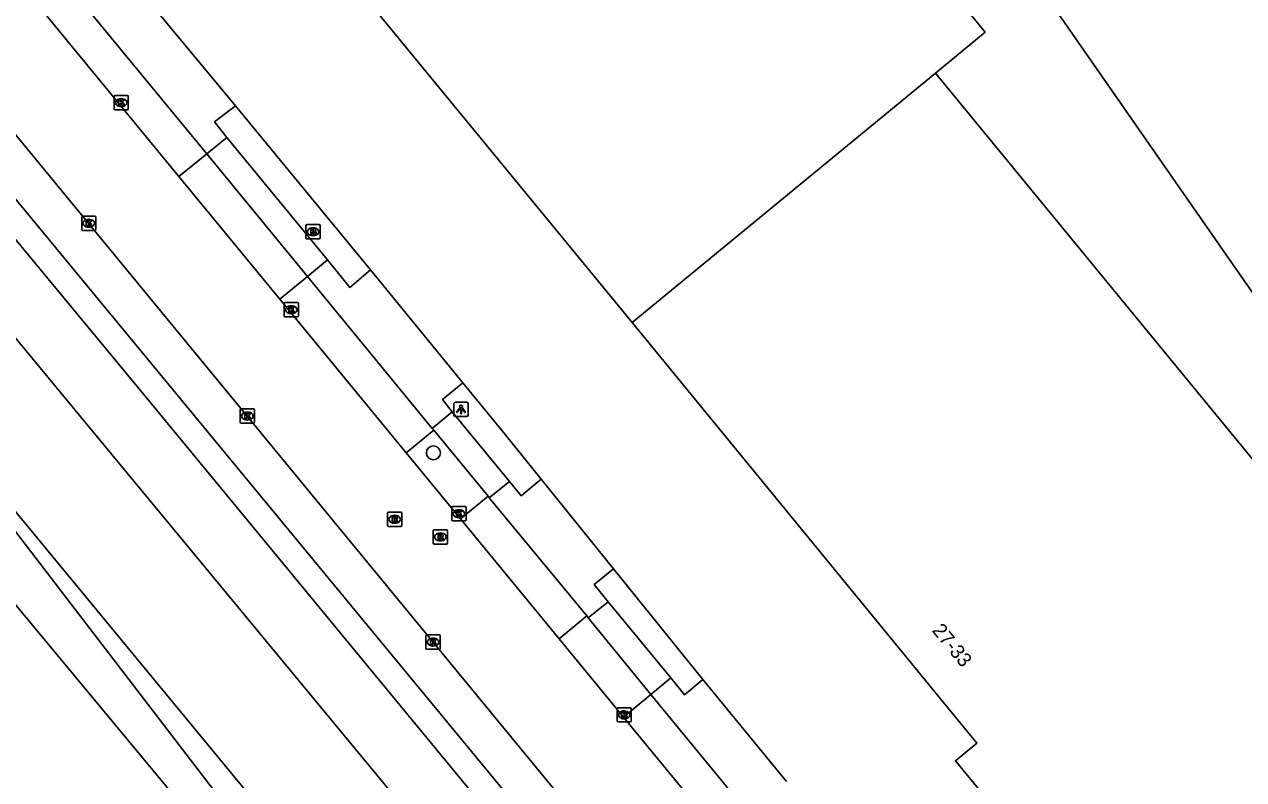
# Model space of a CAD drawing. Extents: x 156651 to 158072, y 387631 to 388990.
# Drawn here: x 157276.7 to 157362.3, y 387691.7 to 387744.8 of the extents above; entities that cross this region are included whole.
import ezdxf

# ---------------------------------------------------------------- set-up
doc = ezdxf.new("R2010")
doc.units = 0
for name, color, linetype in [('IMGEO_Berm_groen', 7, 'Continuous'), ('IMGEO_Boom', 7, 'Continuous'), ('IMGEO_Brandkraan', 7, 'Continuous'), ('IMGEO_Groenvoorziening', 7, 'Continuous'), ('IMGEO_Hek', 7, 'Continuous'), ('IMGEO_Kolk', 7, 'Continuous'), ('IMGEO_Lichtpunt', 7, 'Continuous'), ('IMGEO_Pand', 7, 'Continuous'), ('IMGEO_Pand_nummerreeks', 7, 'Continuous'), ('IMGEO_Rijbaan_lokaal_gesloten', 7, 'Continuous'), ('IMGEO_Rioolput', 7, 'Continuous'), ('IMGEO_Spoor', 7, 'Continuous'), ('IMGEO_Spoorbaan_halfverhard', 7, 'Continuous'), ('IMGEO_Voetpad_open', 7, 'Continuous')]:
    doc.layers.add(name, color=color, linetype=linetype)

msp = doc.modelspace()

# ---------------------------------------------------------------- linework, layer by layer
at = {"layer": 'IMGEO_Berm_groen'}
msp.add_lwpolyline([(157166.96, 387864.35), (157177.251, 387852.02), (157242.391, 387773.236), (157261.602, 387750), (157335.27, 387660.718)], dxfattribs=at)
at = {"layer": 'IMGEO_Boom'}
msp.add_circle((157305.393, 387714.675), 0.489, dxfattribs=at)
at = {"layer": 'IMGEO_Brandkraan'}
for p, q in [((157296.439, 387729.781), (157296.439, 387730.633)), ((157296.514, 387730.707), (157297.366, 387730.707)), ((157296.927, 387730.487), (157296.952, 387730.487)), ((157297.44, 387730.633), (157297.44, 387729.781)), ((157297.366, 387729.707), (157296.514, 387729.707)), ((157296.95, 387729.927), (157296.925, 387729.927))]:
    msp.add_line(p, q, dxfattribs=at)
for points in [[(157296.439, 387729.781), (157296.439, 387730.633)], [(157296.514, 387730.707), (157297.366, 387730.707)], [(157297.44, 387730.633), (157297.44, 387729.781)], [(157297.366, 387729.707), (157296.514, 387729.707)], [(157296.787, 387730.407), (157296.787, 387730.007), (157297, 387730.007)], [(157297.018, 387730.407), (157296.787, 387730.407)], [(157296.966, 387730.326), (157296.912, 387730.326), (157296.912, 387730.25)], [(157296.912, 387730.25), (157296.965, 387730.25)], [(157296.974, 387730.174), (157296.912, 387730.174), (157296.912, 387730.093)], [(157296.912, 387730.093), (157296.974, 387730.093)]]:
    msp.add_lwpolyline(points, dxfattribs=at)
for centre, radius, start, end in [((157296.516, 387730.631), 0.0765, 91.55205, 178.44795), ((157296.516, 387730.631), 0.0765, 91.55205, 178.44795), ((157297.364, 387730.631), 0.0765, 1.55205, 88.44795), ((157297.364, 387730.631), 0.0765, 1.55205, 88.44795), ((157296.516, 387729.783), 0.0765, 181.55205, 268.44795), ((157296.516, 387729.783), 0.0765, 181.55205, 268.44795), ((157296.967, 387730.288), 0.0379, 267.82845, 90.93552), ((157296.975, 387730.133), 0.0404, 269.87594, 90.50774), ((157297.006, 387730.258), 0.251, 268.66757, 293.53466), ((157297.022, 387730.262), 0.145, 59.4692, 91.53667), ((157297.047, 387730.309), 0.0922, 285.51372, 58.15012), ((157297.052, 387730.117), 0.105, 301.31148, 78.98903), ((157297.364, 387729.783), 0.0765, 271.55205, 358.44795), ((157297.364, 387729.783), 0.0765, 271.55205, 358.44795)]:
    msp.add_arc(centre, radius, start, end, dxfattribs=at)
for centre, major_axis, ratio, start_param, end_param in [((157296.926, 387730.207), (-0.387, 0.002), 0.722429, 4.712389, 7.853982), ((157296.951, 387730.207), (-0.39, 0.002), 0.717154, 1.570796, 4.712389)]:
    msp.add_ellipse(centre, major_axis=major_axis, ratio=ratio, start_param=start_param, end_param=end_param, dxfattribs=at)
at = {"layer": 'IMGEO_Groenvoorziening'}
for points in [[(157300.967, 387727.542), (157291.488, 387739.063)], [(157312.956, 387712.823), (157310.43, 387715.954), (157307.465, 387719.585)], [(157324.314, 387698.743), (157318.033, 387706.529)]]:
    msp.add_lwpolyline(points, dxfattribs=at)
at = {"layer": 'IMGEO_Hek'}
for points in [[(157312.956, 387712.823), (157310.43, 387715.954)], [(157318.033, 387706.529), (157312.956, 387712.823)], [(157324.314, 387698.743), (157318.033, 387706.529)], [(157330.19, 387691.592), (157324.314, 387698.743)]]:
    msp.add_lwpolyline(points, dxfattribs=at)
at = {"layer": 'IMGEO_Kolk'}
for p, q in [((157282.963, 387738.851), (157282.963, 387739.703)), ((157283.038, 387739.777), (157283.89, 387739.777)), ((157283.451, 387739.557), (157283.476, 387739.557)), ((157283.964, 387739.703), (157283.964, 387738.851)), ((157283.89, 387738.777), (157283.038, 387738.777)), ((157283.474, 387738.997), (157283.449, 387738.997)), ((157280.69, 387730.376), (157280.69, 387731.228)), ((157280.765, 387731.302), (157281.617, 387731.302)), ((157281.201, 387730.522), (157281.176, 387730.522)), ((157281.178, 387731.082), (157281.203, 387731.082)), ((157281.691, 387731.228), (157281.691, 387730.376)), ((157281.617, 387730.302), (157280.765, 387730.302)), ((157294.912, 387724.304), (157294.912, 387725.156)), ((157294.987, 387725.23), (157295.839, 387725.23)), ((157295.4, 387725.01), (157295.425, 387725.01)), ((157295.913, 387725.156), (157295.913, 387724.304)), ((157295.839, 387724.23), (157294.987, 387724.23)), ((157295.423, 387724.45), (157295.398, 387724.45)), ((157291.827, 387716.832), (157291.827, 387717.684)), ((157291.902, 387717.758), (157292.754, 387717.758)), ((157292.828, 387717.684), (157292.828, 387716.832)), ((157292.754, 387716.758), (157291.902, 387716.758)), ((157292.338, 387716.978), (157292.313, 387716.978)), ((157292.315, 387717.538), (157292.34, 387717.538)), ((157306.687, 387709.972), (157306.687, 387710.824)), ((157306.762, 387710.898), (157307.614, 387710.898)), ((157307.688, 387710.824), (157307.688, 387709.972)), ((157307.198, 387710.118), (157307.173, 387710.118)), ((157307.175, 387710.678), (157307.2, 387710.678)), ((157307.614, 387709.898), (157306.762, 387709.898)), ((157304.867, 387700.958), (157304.867, 387701.81)), ((157304.942, 387701.884), (157305.794, 387701.884)), ((157305.355, 387701.664), (157305.38, 387701.664)), ((157305.868, 387701.81), (157305.868, 387700.958)), ((157305.794, 387700.884), (157304.942, 387700.884)), ((157305.378, 387701.104), (157305.353, 387701.104)), ((157318.293, 387695.844), (157318.293, 387696.696)), ((157318.368, 387696.77), (157319.22, 387696.77)), ((157318.781, 387696.55), (157318.806, 387696.55)), ((157319.294, 387696.696), (157319.294, 387695.844)), ((157319.22, 387695.77), (157318.368, 387695.77)), ((157318.804, 387695.99), (157318.779, 387695.99))]:
    msp.add_line(p, q, dxfattribs=at)
for points in [[(157282.963, 387738.851), (157282.963, 387739.703)], [(157283.038, 387739.777), (157283.89, 387739.777)], [(157283.284, 387739.477), (157283.407, 387739.477), (157283.407, 387739.326), (157283.537, 387739.477), (157283.701, 387739.477), (157283.555, 387739.326), (157283.708, 387739.077), (157283.556, 387739.077), (157283.471, 387739.241), (157283.407, 387739.174), (157283.407, 387739.077), (157283.284, 387739.077), (157283.284, 387739.477)], [(157283.964, 387739.703), (157283.964, 387738.851)], [(157283.89, 387738.777), (157283.038, 387738.777)], [(157280.69, 387730.376), (157280.69, 387731.228)], [(157280.765, 387731.302), (157281.617, 387731.302)], [(157281.011, 387731.002), (157281.134, 387731.002), (157281.134, 387730.851), (157281.264, 387731.002), (157281.428, 387731.002), (157281.282, 387730.851), (157281.435, 387730.602), (157281.283, 387730.602), (157281.198, 387730.766), (157281.134, 387730.699), (157281.134, 387730.602), (157281.011, 387730.602), (157281.011, 387731.002)], [(157281.691, 387731.228), (157281.691, 387730.376)], [(157281.617, 387730.302), (157280.765, 387730.302)], [(157294.912, 387724.304), (157294.912, 387725.156)], [(157294.987, 387725.23), (157295.839, 387725.23)], [(157295.233, 387724.93), (157295.356, 387724.93), (157295.356, 387724.779), (157295.486, 387724.93), (157295.65, 387724.93), (157295.504, 387724.779), (157295.657, 387724.53), (157295.505, 387724.53), (157295.42, 387724.694), (157295.356, 387724.627), (157295.356, 387724.53), (157295.233, 387724.53), (157295.233, 387724.93)], [(157295.913, 387725.156), (157295.913, 387724.304)], [(157295.839, 387724.23), (157294.987, 387724.23)], [(157291.827, 387716.832), (157291.827, 387717.684)], [(157291.902, 387717.758), (157292.754, 387717.758)], [(157292.828, 387717.684), (157292.828, 387716.832)], [(157292.754, 387716.758), (157291.902, 387716.758)], [(157292.148, 387717.458), (157292.271, 387717.458), (157292.271, 387717.307), (157292.401, 387717.458), (157292.565, 387717.458), (157292.419, 387717.307), (157292.572, 387717.058), (157292.42, 387717.058), (157292.335, 387717.222), (157292.271, 387717.155), (157292.271, 387717.058), (157292.148, 387717.058), (157292.148, 387717.458)], [(157306.687, 387709.972), (157306.687, 387710.824)], [(157306.762, 387710.898), (157307.614, 387710.898)], [(157307.688, 387710.824), (157307.688, 387709.972)], [(157307.008, 387710.598), (157307.131, 387710.598), (157307.131, 387710.447), (157307.261, 387710.598), (157307.425, 387710.598), (157307.279, 387710.447), (157307.432, 387710.198), (157307.28, 387710.198), (157307.195, 387710.362), (157307.131, 387710.295), (157307.131, 387710.198), (157307.008, 387710.198), (157307.008, 387710.598)], [(157307.614, 387709.898), (157306.762, 387709.898)], [(157304.867, 387700.958), (157304.867, 387701.81)], [(157304.942, 387701.884), (157305.794, 387701.884)], [(157305.188, 387701.584), (157305.311, 387701.584), (157305.311, 387701.433), (157305.441, 387701.584), (157305.605, 387701.584), (157305.459, 387701.433), (157305.612, 387701.184), (157305.46, 387701.184), (157305.375, 387701.348), (157305.311, 387701.281), (157305.311, 387701.184), (157305.188, 387701.184), (157305.188, 387701.584)], [(157305.868, 387701.81), (157305.868, 387700.958)], [(157305.794, 387700.884), (157304.942, 387700.884)], [(157318.293, 387695.844), (157318.293, 387696.696)], [(157318.368, 387696.77), (157319.22, 387696.77)], [(157318.614, 387696.47), (157318.737, 387696.47), (157318.737, 387696.319), (157318.867, 387696.47), (157319.031, 387696.47), (157318.885, 387696.319), (157319.038, 387696.07), (157318.886, 387696.07), (157318.801, 387696.234), (157318.737, 387696.167), (157318.737, 387696.07), (157318.614, 387696.07), (157318.614, 387696.47)], [(157319.294, 387696.696), (157319.294, 387695.844)], [(157319.22, 387695.77), (157318.368, 387695.77)]]:
    msp.add_lwpolyline(points, dxfattribs=at)
for centre, start, end in [((157283.04, 387739.701), 91.55205, 178.44795), ((157283.04, 387739.701), 91.55205, 178.44795), ((157283.888, 387739.701), 1.55205, 88.44795), ((157283.888, 387739.701), 1.55205, 88.44795), ((157283.04, 387738.853), 181.55205, 268.44795), ((157283.04, 387738.853), 181.55205, 268.44795), ((157283.888, 387738.853), 271.55205, 358.44795), ((157283.888, 387738.853), 271.55205, 358.44795), ((157280.767, 387731.226), 91.55205, 178.44795), ((157280.767, 387731.226), 91.55205, 178.44795), ((157281.615, 387731.226), 1.55205, 88.44795), ((157281.615, 387731.226), 1.55205, 88.44795), ((157280.767, 387730.378), 181.55205, 268.44795), ((157280.767, 387730.378), 181.55205, 268.44795), ((157281.615, 387730.378), 271.55205, 358.44795), ((157281.615, 387730.378), 271.55205, 358.44795), ((157294.989, 387725.154), 91.55205, 178.44795), ((157294.989, 387725.154), 91.55205, 178.44795), ((157295.837, 387725.154), 1.55205, 88.44795), ((157295.837, 387725.154), 1.55205, 88.44795), ((157294.989, 387724.306), 181.55205, 268.44795), ((157294.989, 387724.306), 181.55205, 268.44795), ((157295.837, 387724.306), 271.55205, 358.44795), ((157295.837, 387724.306), 271.55205, 358.44795), ((157291.904, 387717.682), 91.55205, 178.44795), ((157291.904, 387717.682), 91.55205, 178.44795), ((157292.752, 387717.682), 1.55205, 88.44795), ((157292.752, 387717.682), 1.55205, 88.44795), ((157291.904, 387716.834), 181.55205, 268.44795), ((157291.904, 387716.834), 181.55205, 268.44795), ((157292.752, 387716.834), 271.55205, 358.44795), ((157292.752, 387716.834), 271.55205, 358.44795), ((157306.764, 387710.822), 91.55205, 178.44795), ((157306.764, 387710.822), 91.55205, 178.44795), ((157307.612, 387710.822), 1.55205, 88.44795), ((157307.612, 387710.822), 1.55205, 88.44795), ((157306.764, 387709.974), 181.55205, 268.44795), ((157306.764, 387709.974), 181.55205, 268.44795), ((157307.612, 387709.974), 271.55205, 358.44795), ((157307.612, 387709.974), 271.55205, 358.44795), ((157304.944, 387701.808), 91.55205, 178.44795), ((157304.944, 387701.808), 91.55205, 178.44795), ((157305.792, 387701.808), 1.55205, 88.44795), ((157305.792, 387701.808), 1.55205, 88.44795), ((157304.944, 387700.96), 181.55205, 268.44795), ((157304.944, 387700.96), 181.55205, 268.44795), ((157305.792, 387700.96), 271.55205, 358.44795), ((157305.792, 387700.96), 271.55205, 358.44795), ((157318.37, 387696.694), 91.55205, 178.44795), ((157318.37, 387696.694), 91.55205, 178.44795), ((157319.218, 387696.694), 1.55205, 88.44795), ((157319.218, 387696.694), 1.55205, 88.44795), ((157318.37, 387695.846), 181.55205, 268.44795), ((157318.37, 387695.846), 181.55205, 268.44795), ((157319.218, 387695.846), 271.55205, 358.44795), ((157319.218, 387695.846), 271.55205, 358.44795)]:
    msp.add_arc(centre, 0.0765, start, end, dxfattribs=at)
for centre, major_axis, ratio, start_param, end_param in [((157283.45, 387739.277), (-0.387, 0.002), 0.722429, 4.712389, 7.853982), ((157283.475, 387739.277), (-0.39, 0.002), 0.717154, 1.570796, 4.712389), ((157281.177, 387730.802), (-0.387, 0.002), 0.722429, 4.712389, 7.853982), ((157281.202, 387730.802), (-0.39, 0.002), 0.717154, 1.570796, 4.712389), ((157295.399, 387724.73), (-0.387, 0.002), 0.722429, 4.712389, 7.853982), ((157295.424, 387724.73), (-0.39, 0.002), 0.717154, 1.570796, 4.712389), ((157292.314, 387717.258), (-0.387, 0.002), 0.722429, 4.712389, 7.853982), ((157292.339, 387717.258), (-0.39, 0.002), 0.717154, 1.570796, 4.712389), ((157307.174, 387710.398), (-0.387, 0.002), 0.722429, 4.712389, 7.853982), ((157307.199, 387710.398), (-0.39, 0.002), 0.717154, 1.570796, 4.712389), ((157305.354, 387701.384), (-0.387, 0.002), 0.722429, 4.712389, 7.853982), ((157305.379, 387701.384), (-0.39, 0.002), 0.717154, 1.570796, 4.712389), ((157318.78, 387696.27), (-0.387, 0.002), 0.722429, 4.712389, 7.853982), ((157318.805, 387696.27), (-0.39, 0.002), 0.717154, 1.570796, 4.712389)]:
    msp.add_ellipse(centre, major_axis=major_axis, ratio=ratio, start_param=start_param, end_param=end_param, dxfattribs=at)
at = {"layer": 'IMGEO_Lichtpunt'}
for p, q in [((157306.836, 387718.132), (157306.836, 387717.325)), ((157306.836, 387718.132), (157306.836, 387717.325)), ((157307.738, 387718.227), (157306.93, 387718.227)), ((157307.738, 387718.227), (157306.93, 387718.227)), ((157307.832, 387717.325), (157307.832, 387718.132)), ((157307.832, 387717.325), (157307.832, 387718.132)), ((157306.93, 387717.231), (157307.738, 387717.231)), ((157306.93, 387717.231), (157307.738, 387717.231))]:
    msp.add_line(p, q, dxfattribs=at)
for points in [[(157307.21, 387717.796), (157307.249, 387717.768), (157307.061, 387717.506), (157307.023, 387717.533), (157307.21, 387717.796)], [(157307.312, 387717.748), (157307.359, 387717.748), (157307.359, 387717.426), (157307.312, 387717.426), (157307.312, 387717.748)], [(157307.422, 387717.768), (157307.46, 387717.795), (157307.647, 387717.533), (157307.608, 387717.505), (157307.422, 387717.768)]]:
    msp.add_lwpolyline(points, dxfattribs=at)
msp.add_circle((157307.335, 387717.93), 0.0994, dxfattribs=at)
for centre, start, end in [((157306.93, 387718.132), 90, 180), ((157306.93, 387718.132), 90, 180), ((157307.738, 387718.132), 0, 90), ((157307.738, 387718.132), 0, 90), ((157306.93, 387717.325), 180, 270), ((157306.93, 387717.325), 180, 270), ((157307.738, 387717.325), 270, 0), ((157307.738, 387717.325), 270, 360)]:
    msp.add_arc(centre, 0.0946, start, end, dxfattribs=at)
at = {"layer": 'IMGEO_Pand'}
for points in [[(157340.665, 387741.338), (157344.144, 387744.224), (157339.41, 387750), (157308.228, 387788.046), (157294.05, 387776.396), (157292.77, 387777.908), (157288.491, 387774.397), (157289.551, 387773.149), (157287.377, 387771.317), (157286.246, 387772.551), (157280.605, 387767.928), (157290.591, 387755.753), (157292.107, 387757.007), (157297.863, 387750), (157319.262, 387723.952), (157319.361, 387723.831)], [(157377.657, 387704.772), (157382.652, 387708.272), (157387.828, 387700.834), (157398.157, 387708.001), (157392.985, 387715.445), (157400.188, 387720.458), (157379.778, 387749.798), (157380.064, 387750), (157382.282, 387751.568), (157379.431, 387755.676), (157375.106, 387761.905), (157372.57, 387760.157), (157362.197, 387775.069), (157349.501, 387753.181), (157347.656, 387750), (157346.992, 387748.855), (157377.657, 387704.772)], [(157319.361, 387723.831), (157340.665, 387741.338)], [(157319.361, 387723.831), (157343.568, 387694.292), (157342.053, 387693.048), (157358.146, 387673.452), (157364.016, 387678.262), (157361.772, 387681), (157378.748, 387694.956), (157340.665, 387741.338)]]:
    msp.add_lwpolyline(points, dxfattribs=at)
at = {"layer": 'IMGEO_Rijbaan_lokaal_gesloten'}
for points in [[(157337.844, 387661.887), (157244.684, 387775.137), (157168.303, 387867.992)], [(157287.519, 387734.083), (157277.976, 387745.688)], [(157294.606, 387725.465), (157287.519, 387734.083)], [(157303.483, 387714.67), (157294.606, 387725.465)], [(157307.296, 387710.033), (157303.483, 387714.67)], [(157314.215, 387701.619), (157307.296, 387710.033)], [(157318.743, 387696.113), (157314.215, 387701.619)], [(157326.444, 387686.749), (157318.743, 387696.113)]]:
    msp.add_lwpolyline(points, dxfattribs=at)
at = {"layer": 'IMGEO_Rioolput'}
for p, q in [((157302.17, 387709.583), (157302.17, 387710.435)), ((157302.245, 387710.509), (157303.097, 387710.509)), ((157302.658, 387710.289), (157302.683, 387710.289)), ((157303.171, 387710.435), (157303.171, 387709.583)), ((157303.097, 387709.509), (157302.245, 387709.509)), ((157302.681, 387709.729), (157302.656, 387709.729)), ((157305.384, 387708.342), (157305.384, 387709.194)), ((157305.459, 387709.268), (157306.311, 387709.268)), ((157305.872, 387709.048), (157305.897, 387709.048)), ((157306.385, 387709.194), (157306.385, 387708.342)), ((157306.311, 387708.268), (157305.459, 387708.268)), ((157305.895, 387708.488), (157305.87, 387708.488))]:
    msp.add_line(p, q, dxfattribs=at)
for points in [[(157302.17, 387709.583), (157302.17, 387710.435)], [(157302.245, 387710.509), (157303.097, 387710.509)], [(157302.759, 387710.207), (157302.507, 387710.209), (157302.507, 387709.809)], [(157302.507, 387709.809), (157302.631, 387709.809), (157302.631, 387709.971), (157302.642, 387709.971)], [(157302.685, 387710.128), (157302.631, 387710.128), (157302.631, 387710.047)], [(157302.631, 387710.047), (157302.683, 387710.047)], [(157302.689, 387709.942), (157302.76, 387709.809), (157302.9, 387709.809), (157302.835, 387709.935)], [(157303.171, 387710.435), (157303.171, 387709.583)], [(157303.097, 387709.509), (157302.245, 387709.509)], [(157305.384, 387708.342), (157305.384, 387709.194)], [(157305.459, 387709.268), (157306.311, 387709.268)], [(157306.385, 387709.194), (157306.385, 387708.342)], [(157306.311, 387708.268), (157305.459, 387708.268)], [(157305.973, 387708.966), (157305.721, 387708.968), (157305.721, 387708.568)], [(157305.721, 387708.568), (157305.845, 387708.568), (157305.845, 387708.73), (157305.856, 387708.73)], [(157305.899, 387708.887), (157305.845, 387708.887), (157305.845, 387708.806)], [(157305.845, 387708.806), (157305.897, 387708.806)], [(157305.903, 387708.701), (157305.974, 387708.568), (157306.114, 387708.568), (157306.049, 387708.694)]]:
    msp.add_lwpolyline(points, dxfattribs=at)
for centre, radius, start, end in [((157302.247, 387710.433), 0.0765, 91.55205, 178.44795), ((157302.247, 387710.433), 0.0765, 91.55205, 178.44795), ((157302.641, 387709.918), 0.0533, 26.02933, 88.69889), ((157302.667, 387710.236), 0.19, 274.7715, 282.96867), ((157302.691, 387710.032), 0.0964, 77.00612, 93.18647), ((157302.705, 387710.089), 0.0378, 276.66336, 79.67722), ((157302.758, 387710.097), 0.109, 350.36119, 89.41601), ((157302.756, 387710.097), 0.112, 277.58423, 350.98172), ((157302.74, 387709.882), 0.108, 29.51342, 73.79051), ((157303.095, 387710.433), 0.0765, 1.55205, 88.44795), ((157303.095, 387710.433), 0.0765, 1.55205, 88.44795), ((157302.247, 387709.585), 0.0765, 181.55205, 268.44795), ((157302.247, 387709.585), 0.0765, 181.55205, 268.44795), ((157303.095, 387709.585), 0.0765, 271.55205, 358.44795), ((157303.095, 387709.585), 0.0765, 271.55205, 358.44795), ((157305.461, 387709.192), 0.0765, 91.55205, 178.44795), ((157305.461, 387709.192), 0.0765, 91.55205, 178.44795), ((157306.309, 387709.192), 0.0765, 1.55205, 88.44795), ((157306.309, 387709.192), 0.0765, 1.55205, 88.44795), ((157305.461, 387708.344), 0.0765, 181.55205, 268.44795), ((157305.461, 387708.344), 0.0765, 181.55205, 268.44795), ((157305.855, 387708.677), 0.0533, 26.02933, 88.69889), ((157305.881, 387708.995), 0.19, 274.7715, 282.96867), ((157305.905, 387708.791), 0.0964, 77.00612, 93.18647), ((157305.919, 387708.848), 0.0378, 276.66336, 79.67722), ((157305.972, 387708.856), 0.109, 350.36119, 89.41601), ((157305.97, 387708.856), 0.112, 277.58423, 350.98172), ((157305.954, 387708.641), 0.108, 29.51342, 73.79051), ((157306.309, 387708.344), 0.0765, 271.55205, 358.44795), ((157306.309, 387708.344), 0.0765, 271.55205, 358.44795)]:
    msp.add_arc(centre, radius, start, end, dxfattribs=at)
for centre, major_axis, ratio, start_param, end_param in [((157302.657, 387710.009), (-0.387, 0.002), 0.722429, 4.712389, 7.853982), ((157302.682, 387710.009), (-0.39, 0.002), 0.717154, 1.570796, 4.712389), ((157305.871, 387708.768), (-0.387, 0.002), 0.722429, 4.712389, 7.853982), ((157305.896, 387708.768), (-0.39, 0.002), 0.717154, 1.570796, 4.712389)]:
    msp.add_ellipse(centre, major_axis=major_axis, ratio=ratio, start_param=start_param, end_param=end_param, dxfattribs=at)
at = {"layer": 'IMGEO_Spoor'}
for points in [[(156865.308, 388195.462), (156870.022, 388189.509), (156887.814, 388167.443), (156909.51, 388141.178), (156951.276, 388091.519), (156994.8, 388040.336), (157047.715, 387978.302), (157077.25, 387943.427), (157106.481, 387908.588), (157145.615, 387861.584), (157233.331, 387755.475), (157295.4, 387680.676)], [(157182.534, 387835.508), (157234.91, 387772.48), (157331.686, 387655.436), (157334.88, 387651.416), (157341.28, 387643.669)], [(157260.868, 387728.901), (157290.243, 387690.611)], [(157260.868, 387728.901), (157291.476, 387691.848)], [(157291.476, 387691.848), (157334.68, 387639.515)]]:
    msp.add_lwpolyline(points, dxfattribs=at)
at = {"layer": 'IMGEO_Spoorbaan_halfverhard'}
msp.add_lwpolyline([(157345.109, 387646.08), (157317.789, 387679.061), (157284.831, 387719.064), (157252.184, 387758.506), (157223.104, 387793.908), (157216.021, 387802.102), (157185.011, 387839.465), (157165.423, 387862.906)], dxfattribs=at)
at = {"layer": 'IMGEO_Voetpad_open'}
for points in [[(157291.488, 387739.063), (157283.934, 387748.181)], [(157289.472, 387735.682), (157279.921, 387747.288)], [(157290.875, 387736.831), (157290.028, 387737.919), (157291.488, 387739.063)], [(157289.472, 387735.682), (157290.875, 387736.831)], [(157290.875, 387736.831), (157297.954, 387728.245)], [(157289.472, 387735.682), (157287.519, 387734.083)], [(157296.549, 387727.063), (157289.472, 387735.682)], [(157297.954, 387728.245), (157296.549, 387727.063)], [(157300.967, 387727.542), (157299.512, 387726.291), (157297.954, 387728.245)], [(157296.549, 387727.063), (157294.606, 387725.465)], [(157305.305, 387716.387), (157296.549, 387727.063)], [(157307.465, 387719.585), (157300.967, 387727.542)], [(157306.714, 387717.555), (157306.032, 387718.432), (157307.465, 387719.585)], [(157306.714, 387717.555), (157305.305, 387716.387)], [(157310.746, 387712.667), (157306.714, 387717.555)], [(157303.483, 387714.67), (157305.412, 387716.257)], [(157305.412, 387716.257), (157305.305, 387716.387)], [(157305.412, 387716.257), (157309.23, 387711.628)], [(157309.32, 387711.518), (157310.746, 387712.667)], [(157312.956, 387712.823), (157311.56, 387711.66), (157310.746, 387712.667)], [(157318.033, 387706.529), (157312.956, 387712.823)], [(157309.23, 387711.628), (157307.296, 387710.033)], [(157309.32, 387711.518), (157309.23, 387711.628)], [(157316.159, 387703.22), (157309.32, 387711.518)], [(157317.659, 387704.203), (157316.686, 387705.429), (157318.033, 387706.529)], [(157316.272, 387703.083), (157317.659, 387704.203)], [(157317.659, 387704.203), (157322.079, 387698.862)], [(157316.159, 387703.22), (157314.215, 387701.619)], [(157316.272, 387703.083), (157316.159, 387703.22)], [(157320.672, 387697.699), (157316.272, 387703.083)], [(157322.079, 387698.862), (157320.672, 387697.699)], [(157324.314, 387698.743), (157323.018, 387697.677), (157322.079, 387698.862)], [(157330.19, 387691.592), (157324.314, 387698.743)], [(157320.672, 387697.699), (157318.743, 387696.113)], [(157328.377, 387688.339), (157320.672, 387697.699)]]:
    msp.add_lwpolyline(points, dxfattribs=at)

# ---------------------------------------------------------------- texts
at = {"layer": 'IMGEO_Pand_nummerreeks'}
msp.add_text('27-33', height=1, rotation=309.30469, dxfattribs=at).set_placement((157340.368, 387702.181))

doc.saveas('drawing.dxf')
